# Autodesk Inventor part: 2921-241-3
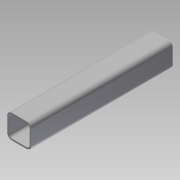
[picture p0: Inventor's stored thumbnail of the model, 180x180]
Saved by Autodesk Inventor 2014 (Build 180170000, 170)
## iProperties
Company: NHTSA/VRTC
Created: 2011-11
Part Number: 2921-241-3
Material: Steel
Document SubType Name: Modeling
Designer: Dave Walker
Density: 7.85 g/cm^3
Project: CHILD SIDE IMPACT SLED
Description: T.S 2" x 2" x 1/8" x 301.8mm (11.88")
Mass: 1328.8 g
Surface Area: 1077.51 cm^2
Volume: 169.273 cm^3
Stock Number: IMPACTOR FRAME TUBE 3
Appearance: Steel
Author: Dave Walker
Title: Impactor Frame Tube 3
Subject: Child Side Impact Sled
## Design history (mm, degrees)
node "Sketch1"
node "2921-105-31"
sketch "Sketch2"
  geometry: L1 (0, 50.8)-(31.496, 50.8) reference; L2 (41.148, 41.148)-(41.148, 9.652) reference; L3 (31.496, 0)-(0, 0) reference; L4 (-9.652, 9.652)-(-9.652, 41.148) reference; L5 (0, 47.625)-(31.496, 47.625) reference; L6 (37.973, 41.148)-(37.973, 9.652) reference; L7 (31.496, 3.175)-(0, 3.175) reference; L8 (-6.477, 9.652)-(-6.477, 41.148) reference; A1 r 9.652 centre (0, 41.148) between (0, 50.8) and (-9.652, 41.148) reference; A2 r 9.652 centre (31.496, 41.148) between (41.148, 41.148) and (31.496, 50.8) reference; A3 r 9.652 centre (31.496, 9.652) between (31.496, 0) and (41.148, 9.652) reference; A4 r 9.652 centre (0, 9.652) between (-9.652, 9.652) and (0, 0) reference; A5 r 6.477 centre (31.496, 41.148) between (37.973, 41.148) and (31.496, 47.625) reference; A6 r 6.477 centre (31.496, 9.652) between (31.496, 3.175) and (37.973, 9.652) reference; A7 r 6.477 centre (0, 9.652) between (-6.477, 9.652) and (0, 3.175) reference; A8 r 6.477 centre (0, 41.148) between (0, 47.625) and (-6.477, 41.148) reference; 1 further point
extrude "Extrusion1" join sketch "Sketch2" distance "d0" = 0.17511; taper "d1" = 0 deg
node "2921-105-3"
node "Base1"
